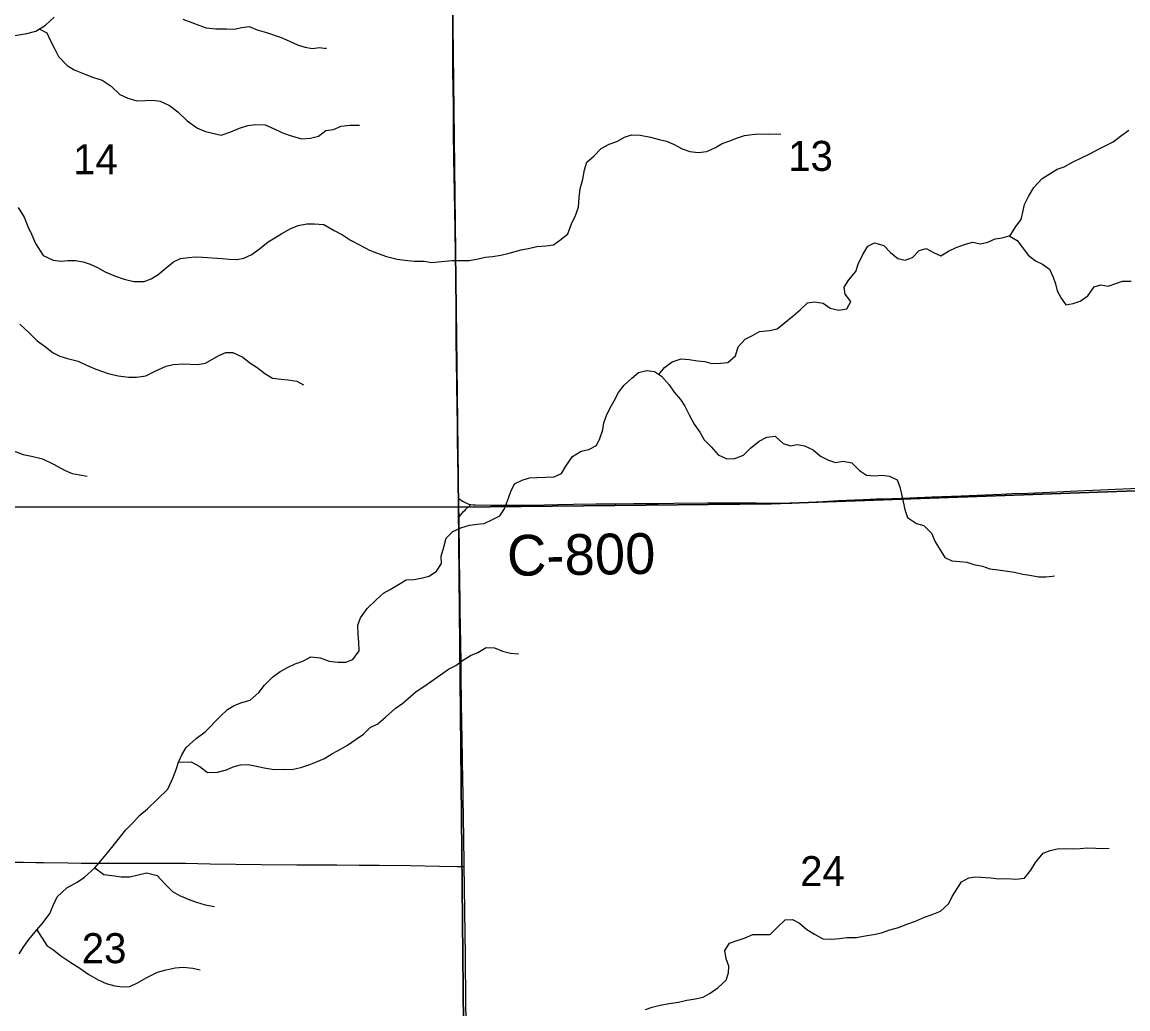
# Model space of a CAD drawing. Extents: x 1874609 to 2204689, y 815661 to 1281160.
# Drawn here: x 2036147 to 2044291, y 1069105 to 1076369 of the extents above; entities that cross this region are included whole.
import ezdxf

# ---------------------------------------------------------------- set-up
doc = ezdxf.new("R2010")
doc.units = 0
for name, color, linetype in [('GM_X_County_Road', 7, 'Continuous'), ('GM_X_County_Road_Text', 7, 'Continuous'), ('GM_X_Minor_River', 7, 'Continuous'), ('GM_X_Section', 7, 'Continuous'), ('GM_X_Section_Text', 7, 'Continuous'), ('GM_X_Township_Road', 7, 'Continuous')]:
    doc.layers.add(name, color=color, linetype=linetype)

msp = doc.modelspace()

# ---------------------------------------------------------------- linework, layer by layer
at = {"layer": 'GM_X_County_Road'}
for points in [[(2039363.1, 1072861.9), (2039361.8, 1072938.9), (2039358.7, 1073037.2), (2039356.4, 1073151.6), (2039354.3, 1073299.2), (2039352.6, 1073397.6), (2039349.2, 1073692.9), (2039346.5, 1073889.9), (2039344.6, 1074004.7), (2039344.2, 1074119.5), (2039343.8, 1074201.4), (2039343, 1074332.2), (2039342.1, 1074414), (2039341.6, 1074463.1), (2039340.3, 1074561.5), (2039339.2, 1074660), (2039336.4, 1074840.4), (2039330.5, 1075119.1), (2039326.2, 1075365.2), (2039325.4, 1075430.7), (2039325.1, 1075496.2), (2039324, 1075611.1), (2039323.1, 1075725.9), (2039320.9, 1075906.4), (2039319.9, 1075988.4), (2039319.5, 1076119.7), (2039319, 1076283.7), (2039319.1, 1076415)], [(2039451.5, 1072818.2), (2039452.8, 1072817.9), (2039469.4, 1072815.7), (2039486, 1072814.7), (2039601.2, 1072813.1), (2039782, 1072813), (2039847.6, 1072814.3), (2039994.7, 1072817), (2040093, 1072819), (2040207.7, 1072821.2), (2040371.7, 1072822.4), (2040519.2, 1072823.9), (2040650.5, 1072825.1), (2040831.1, 1072826.7), (2040945.9, 1072827.3), (2041192.1, 1072829.6), (2041323.5, 1072830.4), (2041553.2, 1072831), (2041717.4, 1072828.7), (2041816.1, 1072829.2), (2041898.1, 1072833), (2042045.7, 1072841.1), (2042160.4, 1072846.6), (2042340.8, 1072854.5), (2042439.2, 1072859.6), (2042553.9, 1072863.5), (2042685.2, 1072867.7), (2042849.2, 1072873.6), (2043062.4, 1072882.5), (2043357.3, 1072895.1), (2043439.2, 1072898.6), (2043554, 1072901.9), (2043718.1, 1072908.9), (2043865.8, 1072915.3), (2044423.3, 1072941.7)], [(2039365, 1072727.9), (2039364.4, 1072791.7), (2039363.1, 1072861.9)], [(2039363.1, 1072861.9), (2039391.4, 1072843.4), (2039405, 1072834.4), (2039420.3, 1072826.9), (2039436.4, 1072821.4), (2039451.5, 1072818.2)], [(2039365, 1072727.9), (2039398.9, 1072766.3), (2039409, 1072777.6), (2039414.3, 1072782.7), (2039420, 1072788.1), (2039427.3, 1072795.2), (2039436.3, 1072803.3), (2039451.5, 1072818.2)], [(2039402.5, 1070153.3), (2039399.1, 1070381.5), (2039397.9, 1070496.3), (2039395.5, 1070676.8), (2039391.4, 1070922.9), (2039387.1, 1071119.8), (2039385.8, 1071185.4), (2039382.2, 1071381.9), (2039380.4, 1071529.4), (2039379.5, 1071660.7), (2039377.7, 1071792), (2039375.6, 1071923.2), (2039374, 1072038), (2039372.4, 1072120), (2039370.2, 1072251.1), (2039368.1, 1072431), (2039367.3, 1072529.3), (2039366.3, 1072611.3), (2039365, 1072726.1), (2039365, 1072727.9)], [(2039419.4, 1068886.6), (2039418.8, 1068921.5), (2039417.3, 1069019.8), (2039415.6, 1069151), (2039412.4, 1069495.6), (2039407.9, 1069823.7), (2039405, 1070004.2), (2039402.5, 1070153.3)]]:
    msp.add_lwpolyline(points, dxfattribs=at)
at = {"layer": 'GM_X_Minor_River'}
for points in [[(2035427.7, 1075792.3), (2035503.5, 1075815.8), (2035553, 1075896.5), (2035584.4, 1075983), (2035607.9, 1076049.4), (2035639.4, 1076123.9), (2035663, 1076174.3), (2035720.8, 1076226.9), (2035794.7, 1076263.6), (2035846.7, 1076278), (2035896.9, 1076276.4), (2035961.2, 1076262.8), (2036021.4, 1076259.2), (2036093.5, 1076269.8), (2036181.7, 1076286.5), (2036247.7, 1076303.1), (2036319.6, 1076347.8), (2036383.3, 1076406.4)], [(2037330.2, 1076391.4), (2037396.6, 1076365.8), (2037448.9, 1076346.1), (2037503.2, 1076326.4), (2037573, 1076318.6)], [(2036273, 1076318.8), (2036330.1, 1076289.6), (2036354.6, 1076235.6), (2036387.2, 1076169.6), (2036415.7, 1076115.6), (2036478.5, 1076049.9), (2036530.9, 1076018.1), (2036615.4, 1075984.6), (2036673.8, 1075961), (2036736.1, 1075941.4), (2036802.7, 1075897.7), (2036865.4, 1075835.9), (2036925.8, 1075808.3), (2036992.1, 1075788.7), (2037056.3, 1075793.2), (2037110.4, 1075795.6), (2037162.6, 1075788), (2037233.1, 1075754.4), (2037293.7, 1075708.6), (2037362.4, 1075642.9), (2037439.1, 1075589.3), (2037497.5, 1075563.6), (2037613, 1075537.5)], [(2037573, 1076318.6), (2037653.7, 1076320.4), (2037707.6, 1076317.9), (2037765.7, 1076329.3), (2037819.8, 1076336.8), (2037877.5, 1076312.2), (2037947.4, 1076293.5), (2038055, 1076256.4), (2038116.7, 1076227.8), (2038174.5, 1076203.2), (2038230.3, 1076184.6), (2038286.2, 1076174), (2038336.3, 1076183.6), (2038388.2, 1076175.1), (2038382.2, 1076177.1)], [(2037613, 1075537.5), (2037683.2, 1075562.8), (2037747.4, 1075588.3), (2037809.6, 1075607.7), (2037867.6, 1075615.1), (2037937.6, 1075612.5), (2037999.3, 1075585.8), (2038059.1, 1075557.2), (2038114.9, 1075536.6), (2038204.6, 1075509.7), (2038270.6, 1075515.1), (2038330.8, 1075530.5), (2038383.1, 1075572.1), (2038439.1, 1075579.6), (2038497.3, 1075603), (2038563.4, 1075610.4), (2038631.3, 1075609.7)], [(2043422.1, 1074792.9), (2043465.4, 1074863.7), (2043503.9, 1074915.4), (2043518.3, 1074971.3), (2043528.8, 1075027.3), (2043559.3, 1075085.1), (2043597.8, 1075150.9), (2043658.4, 1075218.4), (2043710.6, 1075249.9), (2043768.9, 1075287.4), (2043821.1, 1075303), (2043883.3, 1075338.4), (2043953.6, 1075373.8), (2044009.8, 1075399.3), (2044080.1, 1075436.7), (2044132.3, 1075462.2), (2044182.5, 1075487.8), (2044236.8, 1075529.3), (2044297.2, 1075574.8)], [(2037619.3, 1074629.9), (2037671.2, 1074623.4), (2037727.2, 1074622.9), (2037779.3, 1074632.4), (2037839.5, 1074659.8), (2037895.8, 1074701.4), (2037958.2, 1074750.8), (2038008.5, 1074780.4), (2038060.7, 1074814), (2038125, 1074849.4), (2038179.2, 1074870.9), (2038243.3, 1074884.3), (2038297.3, 1074883.8), (2038369.2, 1074879.1), (2038444.8, 1074836.3), (2038506.5, 1074803.6), (2038566.2, 1074763), (2038631.9, 1074730.3), (2038705.5, 1074691.5), (2038769.2, 1074664.8), (2038831.1, 1074644.2), (2038908.9, 1074625.4), (2038964.8, 1074616.9), (2039034.7, 1074610.2), (2039108.7, 1074609.5), (2039164.6, 1074600.9), (2039236.6, 1074606.2), (2039310.6, 1074613.5), (2039378.6, 1074614.9), (2039440.6, 1074614.3), (2039506.7, 1074627.6), (2039556.8, 1074639.2), (2039610.8, 1074644.6), (2039672.9, 1074654.1), (2039735, 1074669.5), (2039823.2, 1074692.7), (2039885.2, 1074704.1), (2039937.3, 1074717.6), (2040003.4, 1074723), (2040059.4, 1074730.4), (2040113.7, 1074770), (2040166.1, 1074811.6), (2040192.7, 1074883.4), (2040223.2, 1074945.2), (2040243.7, 1075007.1), (2040250.3, 1075079.2), (2040256.8, 1075143.2), (2040275.4, 1075213.1), (2040290, 1075281.1), (2040306.5, 1075339.1), (2040360.9, 1075384.6), (2040411.3, 1075438.2), (2040471.6, 1075469.7), (2040527.7, 1075489.2), (2040584, 1075522.7), (2040636.1, 1075540.2), (2040698.1, 1075537.6), (2040773.9, 1075522.8), (2040837.7, 1075506.2), (2040891.6, 1075493.6), (2040943.4, 1075471.1), (2041007.1, 1075436.4), (2041064.9, 1075417.8), (2041124.8, 1075409.2), (2041188.9, 1075416.6), (2041253.1, 1075446.1), (2041303.3, 1075475.6), (2041359.5, 1075495.1), (2041415.7, 1075518.6), (2041467.8, 1075534.1), (2041523.8, 1075541.6), (2041573.9, 1075547.1), (2041643.8, 1075544.4), (2041701.8, 1075545.9), (2041733.8, 1075545.6)], [(2036117.9, 1075005.5), (2036162.7, 1074933.6), (2036189.3, 1074863.5), (2036215.9, 1074807.5), (2036246.5, 1074739.5), (2036301.4, 1074651.6), (2036375.9, 1074616), (2036434.1, 1074610.4), (2036484.2, 1074614.8), (2036540.4, 1074613.2), (2036596.7, 1074603.6), (2036648.9, 1074587.9), (2036703.3, 1074562.3), (2036757.7, 1074530.6), (2036826.2, 1074500.9), (2036898.6, 1074477.4), (2036970.9, 1074459.9), (2037045.2, 1074460.4), (2037097.2, 1074478.9), (2037149, 1074511.4), (2037206.8, 1074560), (2037262.6, 1074604.5), (2037314.6, 1074629), (2037372.7, 1074637.4), (2037424.8, 1074641.9), (2037475, 1074638.2), (2037619.3, 1074629.9)], [(2040836.8, 1073776.1), (2040877.4, 1073827.1), (2040933.8, 1073868.6), (2041001.9, 1073890), (2041059.9, 1073885.4), (2041121.8, 1073874.8), (2041175.7, 1073870.3), (2041227.6, 1073855.7), (2041291.6, 1073859.1), (2041345.6, 1073862.6), (2041402, 1073912.1), (2041420.6, 1073980.1), (2041473, 1074035.6), (2041527.2, 1074061.2), (2041577.5, 1074090.7), (2041651.5, 1074098), (2041707.6, 1074111.5), (2041759.9, 1074153.1), (2041826.4, 1074206.5), (2041876.7, 1074252.1), (2041931.1, 1074301.6), (2041983.2, 1074309.1), (2042047.1, 1074300.5), (2042098.8, 1074263.9), (2042162.6, 1074249.3), (2042220.7, 1074258.8), (2042251.1, 1074312.6), (2042209.6, 1074367), (2042202.1, 1074419.2), (2042234.5, 1074473), (2042287, 1074534.6), (2042303.5, 1074588.5), (2042338, 1074658.3), (2042374.6, 1074720), (2042424.8, 1074745.6), (2042492.6, 1074724.9), (2042542.1, 1074674.3), (2042597.7, 1074629.7), (2042649.6, 1074617.2), (2042703.8, 1074636.7), (2042754.2, 1074688.3), (2042806.3, 1074701.8), (2042860, 1074673.2), (2042913.8, 1074648.7), (2042970.1, 1074684.2), (2043026.3, 1074709.7), (2043088.4, 1074731.1), (2043146.6, 1074748.6), (2043206.5, 1074738), (2043258.5, 1074749.5), (2043312.7, 1074775), (2043364.8, 1074780.5), (2043416.9, 1074796.1), (2043474.6, 1074761.4), (2043514.1, 1074709), (2043555.6, 1074652.5), (2043611.2, 1074611.9), (2043663, 1074587.3), (2043714.7, 1074550.8), (2043740.2, 1074492.4), (2043757.7, 1074442.2), (2043769.3, 1074392), (2043798.8, 1074337.6), (2043834.4, 1074287.2), (2043888.5, 1074298.7), (2043938.6, 1074314.2), (2043994.9, 1074353.7), (2044041.5, 1074419.4), (2044091.6, 1074434.9), (2044145.5, 1074426.4), (2044201.6, 1074445.9), (2044251.8, 1074463.4), (2044315.7, 1074462.8)], [(2036131, 1074146.6), (2036199.7, 1074082.9), (2036258.4, 1074023.1), (2036308.8, 1073985.3), (2036375.5, 1073933.7), (2036425.8, 1073909.9), (2036480.1, 1073892.3), (2036560.5, 1073872.8), (2036620.9, 1073843.1), (2036689.4, 1073815.6), (2036781.9, 1073782.1), (2036854.2, 1073766.6), (2036932.6, 1073755.1), (2036988.7, 1073755.6), (2037056.9, 1073766.1), (2037132.8, 1073802.8), (2037208.7, 1073837.5), (2037258.8, 1073849.9), (2037335, 1073854.4), (2037385.1, 1073850.8), (2037439.3, 1073849.2), (2037497.4, 1073857.6), (2037595.2, 1073915)], [(2037595.2, 1073915), (2037647.4, 1073936.6), (2037699.4, 1073936.1), (2037773.1, 1073903.3), (2037824.7, 1073860.7), (2037878.4, 1073826.1), (2037934, 1073783.5), (2037991.7, 1073748.9), (2038055.6, 1073740.3), (2038107.6, 1073735.8), (2038169.4, 1073725.2), (2038219.2, 1073698.6)], [(2037608.6, 1071258.9), (2037659, 1071308.5), (2037709.2, 1071338), (2037765.4, 1071361.5), (2037827.5, 1071378.9), (2037890, 1071434.4), (2037932.4, 1071488.1), (2037990.9, 1071547.6), (2038047.2, 1071589.1), (2038105.5, 1071620.6), (2038157.7, 1071646.1), (2038213.8, 1071665.6), (2038274.1, 1071697.1), (2038342, 1071688.4), (2038407.8, 1071665.7), (2038471.7, 1071657.1), (2038531.7, 1071658.5), (2038583.8, 1071678.1), (2038630.4, 1071741.7), (2038626.9, 1071803.8), (2038621.4, 1071862), (2038620, 1071930.1), (2038638.4, 1071984), (2038689, 1072051.6), (2038753.5, 1072117.1), (2038807.9, 1072164.6), (2038858.1, 1072192.1), (2038918.4, 1072229.6), (2038974.7, 1072263.1), (2039030.7, 1072266.6), (2039086.8, 1072276.1), (2039144.9, 1072289.5), (2039199.2, 1072327), (2039235.7, 1072384.8), (2039234.1, 1072436.9), (2039252.7, 1072504.8), (2039269.2, 1072570.7), (2039319.6, 1072618.3), (2039377.8, 1072645.8), (2039442, 1072665.2), (2039498, 1072672.7), (2039550.1, 1072678.2), (2039612.3, 1072707.6), (2039664.5, 1072735.1), (2039698.9, 1072786.9), (2039721.4, 1072844.8), (2039746, 1072914.6), (2039774.5, 1072970.4), (2039830.7, 1072997.9), (2039884.8, 1073013.4), (2039938.8, 1073016.9), (2040000.8, 1073018.3), (2040064.8, 1073021.7), (2040119, 1073047.2), (2040151.5, 1073101), (2040200.1, 1073172.6), (2040264.4, 1073210.1), (2040320.5, 1073223.5), (2040376.7, 1073253), (2040401.1, 1073304.9), (2040423.7, 1073366.8), (2040432.1, 1073418.8), (2040450.6, 1073472.7), (2040477, 1073530.5), (2040507.5, 1073582.3), (2040540, 1073642.1), (2040580.4, 1073697.8), (2040636.8, 1073747.3), (2040687.2, 1073790.9), (2040747.3, 1073804.3), (2040803.2, 1073797.8), (2040856.9, 1073763.2), (2040912.3, 1073698.5), (2040949.9, 1073646.1), (2040995.4, 1073591.6), (2041027, 1073541.2), (2041060.4, 1073478.8), (2041095.8, 1073410.3), (2041137.3, 1073349.8), (2041170.8, 1073293.4), (2041222.3, 1073242.8), (2041273.8, 1073184.2), (2041337.5, 1073153.6), (2041395.6, 1073157), (2041459.7, 1073180.4), (2041512.2, 1073232), (2041574.6, 1073285.5), (2041632.8, 1073315), (2041692.8, 1073320.4), (2041752.4, 1073267.7), (2041806.2, 1073249.2), (2041856.3, 1073260.7), (2041910.2, 1073250.2), (2041971.9, 1073219.5), (2042027.5, 1073172.9), (2042085.2, 1073144.3), (2042137.1, 1073127.8), (2042195.1, 1073137.2), (2042257, 1073124.6), (2042314.5, 1073068), (2042366.2, 1073033.4)], [(2036084.5, 1073213), (2036154.9, 1073187.5), (2036217.2, 1073173.9), (2036297.6, 1073154.4), (2036378.2, 1073114.9), (2036464.8, 1073069.3), (2036515.1, 1073045.6), (2036569.4, 1073036), (2036625.6, 1073026.4)], [(2042366.2, 1073033.4), (2042424.1, 1073028.9), (2042482.2, 1073034.3), (2042534.1, 1073025.8), (2042591.8, 1072999.2), (2042611.4, 1072948.9), (2042622.9, 1072894.7), (2042636.4, 1072838.5), (2042648, 1072782.3), (2042667.4, 1072722), (2042735, 1072677.3), (2042788.9, 1072664.8), (2042844.4, 1072608.2), (2042871.8, 1072543.8), (2042909.3, 1072485.3), (2042942.8, 1072426.9), (2042994.6, 1072404.4), (2043052.6, 1072399.8), (2043104.5, 1072393.3), (2043156.3, 1072376.8), (2043220.2, 1072364.1), (2043274, 1072345.6), (2043335.9, 1072337), (2043403.8, 1072326.3), (2043455.7, 1072319.8), (2043517.6, 1072305.2), (2043569.5, 1072298.7), (2043633.4, 1072286), (2043685.4, 1072285.5), (2043735.4, 1072291.1), (2043749.4, 1072292.9)], [(2037585, 1070848.5), (2037651.2, 1070865.9), (2037701.3, 1070887.5), (2037755.4, 1070901), (2037811.5, 1070904.4), (2037873.3, 1070891.8), (2037929.2, 1070879.2), (2038003.1, 1070868.5), (2038077.1, 1070869.8), (2038133, 1070867.2), (2038199.1, 1070882.6), (2038265.3, 1070904), (2038315.5, 1070923.6), (2038373.7, 1070949), (2038434, 1070986.5), (2038492.2, 1071016), (2038542.4, 1071045.5), (2038606.8, 1071091), (2038661.1, 1071126.5), (2038711.5, 1071176.1), (2038765.7, 1071203.6), (2038824.1, 1071253.1), (2038894.6, 1071316.5), (2038951, 1071356), (2039049.6, 1071441.2), (2039106, 1071478.7), (2039162.3, 1071518.2), (2039287, 1071605.1), (2039341.2, 1071632.6), (2039391.5, 1071670.2), (2039449.8, 1071707.7), (2039504, 1071729.2), (2039564.2, 1071764.7), (2039626.2, 1071762.1), (2039686, 1071739.5), (2039743.8, 1071724.9), (2039799.8, 1071718.3), (2039797.7, 1071714.3)], [(2036124.8, 1069511), (2036160.4, 1069563.4), (2036196.1, 1069615.8), (2036255.7, 1069686.5), (2036301.4, 1069741), (2036351, 1069807.6), (2036374.6, 1069866), (2036406.2, 1069930.4), (2036475.8, 1069997.2), (2036551.7, 1070037.9), (2036607.6, 1070074.4), (2036681.3, 1070143.1), (2036727, 1070195.7), (2036774.6, 1070254.2), (2036828.3, 1070318.8), (2036911.6, 1070423.8), (2036965.4, 1070476.4), (2037015.1, 1070530.9), (2037070.9, 1070577.5), (2037140.5, 1070646.2), (2037220.1, 1070723), (2037257.6, 1070803.6), (2037281.1, 1070868), (2037298.8, 1070920.3), (2037322.4, 1070974.6), (2037356, 1071029.1), (2037429.7, 1071095.8), (2037495.5, 1071144.5), (2037608.6, 1071258.9)], [(2037298.8, 1070920.3), (2037391, 1070923), (2037455.5, 1070889.3), (2037512, 1070845.6), (2037585, 1070848.5)], [(2042971, 1069880.9), (2042997.5, 1069932.8), (2043066.4, 1070040.2), (2043120.6, 1070069.8), (2043170.6, 1070077.3), (2043282.6, 1070070.2), (2043340.5, 1070063.6), (2043400.5, 1070065), (2043466.4, 1070060.4), (2043528.5, 1070067.8), (2043576.9, 1070125.4), (2043611.4, 1070183.1), (2043666, 1070252.7), (2043718.1, 1070272.2), (2043770.2, 1070283.8), (2043828.2, 1070285.2), (2043880.2, 1070282.7), (2043940.2, 1070286.1), (2043992.2, 1070291.6), (2044054.2, 1070289), (2044112.1, 1070286.4), (2044154.1, 1070288)], [(2036681.3, 1070143.1), (2036747.8, 1070095.5), (2036826.2, 1070084), (2036876.4, 1070078.4), (2036940.6, 1070076.8), (2037002.6, 1070091.3), (2037062.7, 1070107.8), (2037141.1, 1070088.4), (2037203.8, 1070020.6), (2037254.4, 1069968.8), (2037306.8, 1069939.1), (2037381.2, 1069907.5), (2037431.5, 1069889.8), (2037493.9, 1069872.2), (2037564.2, 1069858.7)], [(2040737.1, 1069101.5), (2040787.2, 1069117), (2040847.3, 1069132.5), (2040913.4, 1069143.8), (2040981.5, 1069155.2), (2041041.6, 1069170.6), (2041091.6, 1069176.1), (2041161.7, 1069191.5), (2041214, 1069221), (2041272.3, 1069262.5), (2041332.7, 1069316), (2041349.2, 1069369.9), (2041351.6, 1069420), (2041332.1, 1069474.2), (2041322.6, 1069534.4), (2041357.1, 1069590.2), (2041413.2, 1069609.6), (2041471.4, 1069629.1), (2041527.5, 1069652.6), (2041595.5, 1069651.9), (2041657.5, 1069653.3), (2041709.9, 1069706.9), (2041766.4, 1069760.4), (2041820.4, 1069763.9), (2041872.2, 1069737.4), (2041925.7, 1069688.8), (2041983.4, 1069654.2), (2042043.1, 1069621.6), (2042107.1, 1069618.9), (2042167.1, 1069624.4), (2042221.1, 1069631.8), (2042291.1, 1069631.2), (2042355.2, 1069642.6), (2042417.2, 1069652), (2042475.4, 1069665.4), (2042537.5, 1069686.8), (2042601.6, 1069704.3), (2042669.8, 1069731.6), (2042726, 1069751.1), (2042792.2, 1069780.5), (2042850.4, 1069800), (2042910.6, 1069825.4), (2042971, 1069880.9)], [(2036255.7, 1069686.5), (2036328.9, 1069572.7), (2036379.3, 1069536.9), (2036431.8, 1069495.2), (2036506.4, 1069445.6), (2036573, 1069403.9), (2036637.5, 1069358.2), (2036706, 1069318.6), (2036766.4, 1069293), (2036830.8, 1069275.4), (2036885, 1069267.8), (2036939.1, 1069270.2), (2036997.1, 1069296.7), (2037065, 1069335.3), (2037144.9, 1069376), (2037208.9, 1069392.6), (2037275, 1069407.1), (2037333.1, 1069411.5), (2037403.4, 1069406.1), (2037457.7, 1069392.4)]]:
    msp.add_lwpolyline(points, dxfattribs=at)
at = {"layer": 'GM_X_Section'}
for points in [[(2044543.3, 1078169), (2044675.8, 1072892.3), (2044483.6, 1072923.6), (2041664.2, 1072823.7), (2039360.9, 1072797.6), (2039298.6, 1078020.5), (2041866.1, 1078033.5), (2043624.7, 1078159.7)], [(2034034, 1078081.8), (2039298.6, 1078020.5), (2039360.9, 1072797.6), (2034097, 1072800.8)], [(2039360.9, 1072797.6), (2041664.2, 1072823.7), (2044483.6, 1072923.6), (2044675.8, 1072892.3), (2044748.5, 1067571.4), (2039413.6, 1067474.7)], [(2034097, 1072800.8), (2039360.9, 1072797.6), (2039413.6, 1067474.7), (2034142, 1067529.9)]]:
    msp.add_lwpolyline(points, close=True, dxfattribs=at)
at = {"layer": 'GM_X_Township_Road'}
for points in [[(2034336.7, 1070193.1), (2034499.7, 1070191.4), (2034713.1, 1070191.5), (2034828, 1070190.5), (2034991.9, 1070189.4), (2035319.7, 1070190), (2035385.3, 1070190.5), (2035516.4, 1070189.9), (2035631.2, 1070188.8), (2035713.3, 1070188.9), (2035795.3, 1070188.7), (2035910, 1070187.3), (2036008.3, 1070186.1), (2036073.9, 1070185.7), (2036155.9, 1070185.2), (2036247, 1070183.9)], [(2036247, 1070183.9), (2036303.4, 1070183), (2036483.6, 1070179.9), (2036582, 1070179.2), (2036729.7, 1070177.5), (2036811.7, 1070176.9), (2036893.5, 1070177), (2037072.8, 1070178.2), (2037203.6, 1070178.4), (2037351, 1070177.2), (2037531.4, 1070173.7), (2037908.3, 1070167.8), (2038170.8, 1070166.3), (2038466, 1070164.6), (2038630.1, 1070163.3), (2038777.7, 1070163.5), (2039007.5, 1070161), (2039220.7, 1070155.6), (2039351.9, 1070153.7), (2039402.5, 1070153.3)]]:
    msp.add_lwpolyline(points, dxfattribs=at)

# ---------------------------------------------------------------- texts
at = {"layer": 'GM_X_County_Road_Text'}
msp.add_text('C-800', height=300, rotation=0.82606, dxfattribs=at).set_placement((2039720.3, 1072292.8))
at = {"layer": 'GM_X_Section_Text'}
for s, p in [('13', (2041789.3, 1075274)), ('14', (2036522.5, 1075249.2)), ('24', (2041877.3, 1070008.8)), ('23', (2036586.3, 1069441.8))]:
    msp.add_text(s, height=221, rotation=0.00001, dxfattribs=at).set_placement(p)

doc.saveas('drawing.dxf')
